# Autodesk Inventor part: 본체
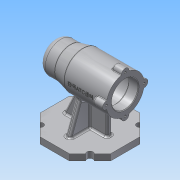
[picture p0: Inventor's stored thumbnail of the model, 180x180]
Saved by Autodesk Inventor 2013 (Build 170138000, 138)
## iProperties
Created: 2019-12
Part Number: 본체
Material: 알루미늄 6061
Document SubType Name: Modeling
Designer: Administrator
Density: 2.71 g/cm^3
Mass: 728.494 g
Surface Area: 714.679 cm^2
Volume: 268.817 cm^3
Author: Administrator
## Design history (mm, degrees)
sketch "스케치1"
  geometry: C1 r 30 at (0, 0); 1 further point
  constraints: 1 centre point, 1 coincident
  dimensions: "d0" = 60 diameter of C1
extrude "돌출1" new body sketch "스케치1" distance "d2" = 67; taper "d3" = 0 deg
sketch "스케치2"
  geometry: C1 r 30 at (0, 0) reference; C2 r 25 at (0, 0)
  constraints: 1 centre point, 1 coincident
  dimensions: "d4" = 50 diameter of C2
extrude "돌출2" join sketch "스케치2" distance "d6" = 45; taper "d7" = 0 deg
sketch "스케치3"
  geometry: L1 (25, 67)-(25, 112) reference; L2 (30, 0)-(30, 67) reference; L3 (0, 0)-(0, 126.756); L4 (25, 87)-(30, 67); L5 (30, 67)-(-30, 67) reference
  constraints: 4 end point, 1 point on line, 1 vertical
  dimensions: "d8" = 25 distance of L1.end L4.start
revolve "회전1" sketch "스케치3" stored, may be unused: angle "d9" = 90 deg
sketch "스케치4"
  geometry: C1 r 30 at (0, 0) reference; C2 r 21 at (0, 0)
  constraints: 1 centre point, 1 coincident
  dimensions: "d10" = 42 diameter of C2
extrude "돌출3" cut sketch "스케치4" distance "d12" = 15; taper "d13" = 0 deg
sketch "스케치5"
  geometry: C1 r 21 at (0, 0) reference; C2 r 24 at (0, 0)
  constraints: 1 centre point, 1 coincident
  dimensions: "d14" = 48 diameter of C2
extrude "돌출4" cut sketch "스케치5" distance "d16" = 54; taper "d17" = 0 deg
sketch "스케치6"
  geometry: C1 r 21 at (0, 0); 1 further point
  constraints: 1 centre point, 1 coincident
  dimensions: "d18" = 42 diameter of C1
extrude "돌출5" cut sketch "스케치6" distance "d20" = 12; taper "d21" = 0 deg
sketch "스케치9"
  geometry: C1 r 17.5 at (0, 0); 1 further point
  constraints: 1 centre point, 1 coincident
  dimensions: "d30" = 35 diameter of C1
extrude "돌출8" cut sketch "스케치9" distance "d32" = 18; taper "d33" = 0 deg
sketch "스케치10"
  geometry: C1 r 16 at (0, 0); 1 further point
  constraints: 1 centre point, 1 coincident
  dimensions: "d34" = 32 diameter of C1
extrude "돌출9" cut sketch "스케치10" distance "d36" = 4; taper "d37" = 0 deg
sketch "스케치11"
  geometry: C1 r 16 at (0, 0) reference; C2 r 10.5 at (0, 0)
  constraints: 1 centre point, 1 coincident
  dimensions: "d38" = 21 diameter of C2
extrude "돌출10" cut sketch "스케치11" distance "d40" = 3; taper "d41" = 0 deg
fillet "모깎기1" dims "d42" = 10
sketch "스케치12"
  geometry: A1 r 30 centre (0, 0) between (0, 30) and (-5.97, 29.4) reference; A2 r 6 centre (0, 30) between (5.97, 29.4) and (-5.97, 29.4); 1 further point
  constraints: 5 point on circle, 1 centre point, 1 vertical alignment
  dimensions: "d43" = 12 diameter of A2
extrude "돌출11" join sketch "스케치12" distance "d45" = 16; taper "d46" = 0 deg
sketch "스케치13"
  geometry: A1 r 6 centre (0, 30) between (5.97, 29.4) and (-5.97, 29.4) reference; 1 further point
  constraints: 1 coincident
hole "구멍1" sketch "스케치13" at (0, 30) diameter "d47" = 3.242; stored, may be unused: countersink angle "d51" = 90 deg, drill point angle "d53" = 118 deg; dims "d48" = 8, "d49" = 4, "d50" = 2, "d52" = 11
fillet "모깎기2" dims "d57" = 3
fillet "모깎기3" dims "d58" = 3
fillet "모깎기4" dims "d59" = 0.3
fillet "모깎기5" dims "d60" = 3
chamfer "모따기1" distance "d66" = 1; stored, may be unused: second distance "d67" = 2, angle "d68" = 45 deg
node "작업 평면1"
sketch "스케치14"
  geometry: L1 (-23.196, 0)-(-56, 32.804); L2 (-56, 32.804)-(-56, 79.196); L3 (-56, 79.196)-(-23.196, 112); L4 (-23.196, 112)-(23.196, 112); L5 (23.196, 112)-(56, 79.196); L6 (56, 79.196)-(56, 32.804); L7 (56, 32.804)-(23.196, 0); L8 (23.196, 0)-(-23.196, 0); L9 (-39.598, 95.598)-(39.598, 16.402); L10 (39.598, 95.598)-(-39.598, 16.402); L11 (-29.4, 0)-(-5.97, 0) reference; C1 r 5 at (-39.598, 16.402); C2 r 5 at (39.598, 16.402); C3 r 5 at (39.598, 95.598); C4 r 5 at (-39.598, 95.598); A1 r 56 centre (0, 56) between (-39.598, 95.598) and (39.598, 95.598); 4 further points
  constraints: 20 end point, 6 coincident, 5 centre point, 4 midpoint, 4 point on circle, 3 equal radius, 2 perpendicular, 1 collinear, 1 vertical alignment, 17 other
  dimensions: "d70" = 112 diameter of A1; "d72" = 56 distance from line of L6 A1.centre; "d73" = 90 deg angle of L10 L9 (derived); "d74" = 45 deg dimension on A1.centre L9.start point (-56, 56) (derived); "d75" = 10 diameter of C4
extrude "돌출12" join sketch "스케치14" distance "d76" = 10; taper "d77" = 0 deg
extrude "돌출13" cut sketch "스케치14" distance "d78" = 10; taper "d79" = 0 deg
node "작업 평면2"
sketch "스케치16"
  geometry: L1 (-10, -12.804)-(-56.766, 4.217); L2 (-56.766, 42.174)-(-10, 59.196); L3 (0, -32.804)-(-10, -32.804) reference; L4 (-10, -19.938)-(-10, -11.402) reference; L5 (0, 79.196)-(-10, 79.196) reference; L6 (-10, 57.794)-(-10, 66.329) reference; L7 (-10, 0)-(-10, -12.866) reference; L8 (-10, 46.392)-(-10, 0) reference; L9 (-10, 59.258)-(-10, 46.392) reference; A1 r 30 centre (-80, 23.196) between (-56.766, 4.217) and (-56.766, 42.174) reference; 1 further point
  constraints: 4 end point, 2 point on circle, 2 point on line
  dimensions: "d85" = 20 distance from line of L1.start L3; "d86" = 110 deg angle of L1 L4; "d87" = 20 distance from line of L5 L2.end; "d89" = 110 deg angle of L6 L2
extrude "돌출14" join sketch "스케치16" stored distance "d90" = 8; taper "d91" = 0 deg
sketch "스케치17"
  geometry: L1 (28.131, 74.476)-(70, 94); L2 (30, 25)-(70, 25); L3 (80, 0)-(70, 0) reference; L4 (80, 112)-(70, 112) reference; L5 (70, 112)-(70, 99.134) reference; L6 (30, 16)-(30, 66.631) reference; L7 (70, 32.804)-(70, 19.938) reference; L8 (70, 90.598)-(70, 99.134) reference; L9 (25.09, 86.642)-(29.91, 67.358) reference; 2 further points
  constraints: 4 end point, 4 point on line, 1 horizontal
  dimensions: "d92" = 25 distance between parallel lines of L2 L3; "d93" = 18 distance from line of L4 L1.end; "d95" = 115 deg angle of L8 L1
feature "리브1" dims "d96" = 1, "d97" = 8, "d98" = 0, "d99" = 0, "d100" = 1, "d101" = 1
feature "리브2" dims "d102" = 1, "d103" = 8, "d104" = 0, "d105" = 0, "d106" = 1, "d107" = 1
fillet "모깎기8" dims "d108" = 3
fillet "모깎기9" dims "d109" = 3
node "작업 평면3"
sketch "스케치19"
  geometry: L1 (-29.4, 0)-(-5.97, 0) reference; 2 further points
  constraints: 1 vertical alignment, 1 other
  dimensions: "d111" = 41 distance from line of point (0, 41) L1
feature "엠보싱1" sketch "스케치19" dims "d0" = 60, "d112" = 0.5, "d113" = 0
fillet "모깎기10" dims "d114" = 3
fillet "모깎기11" dims "d115" = 1
node "솔리드1"
pattern_circular "원형 패턴1" dims angle "d55" = 360 deg
pattern_circular "원형 패턴3" dims angle "d117" = 360 deg
other parameters: "d84" = -56, "d110" = -175.75
